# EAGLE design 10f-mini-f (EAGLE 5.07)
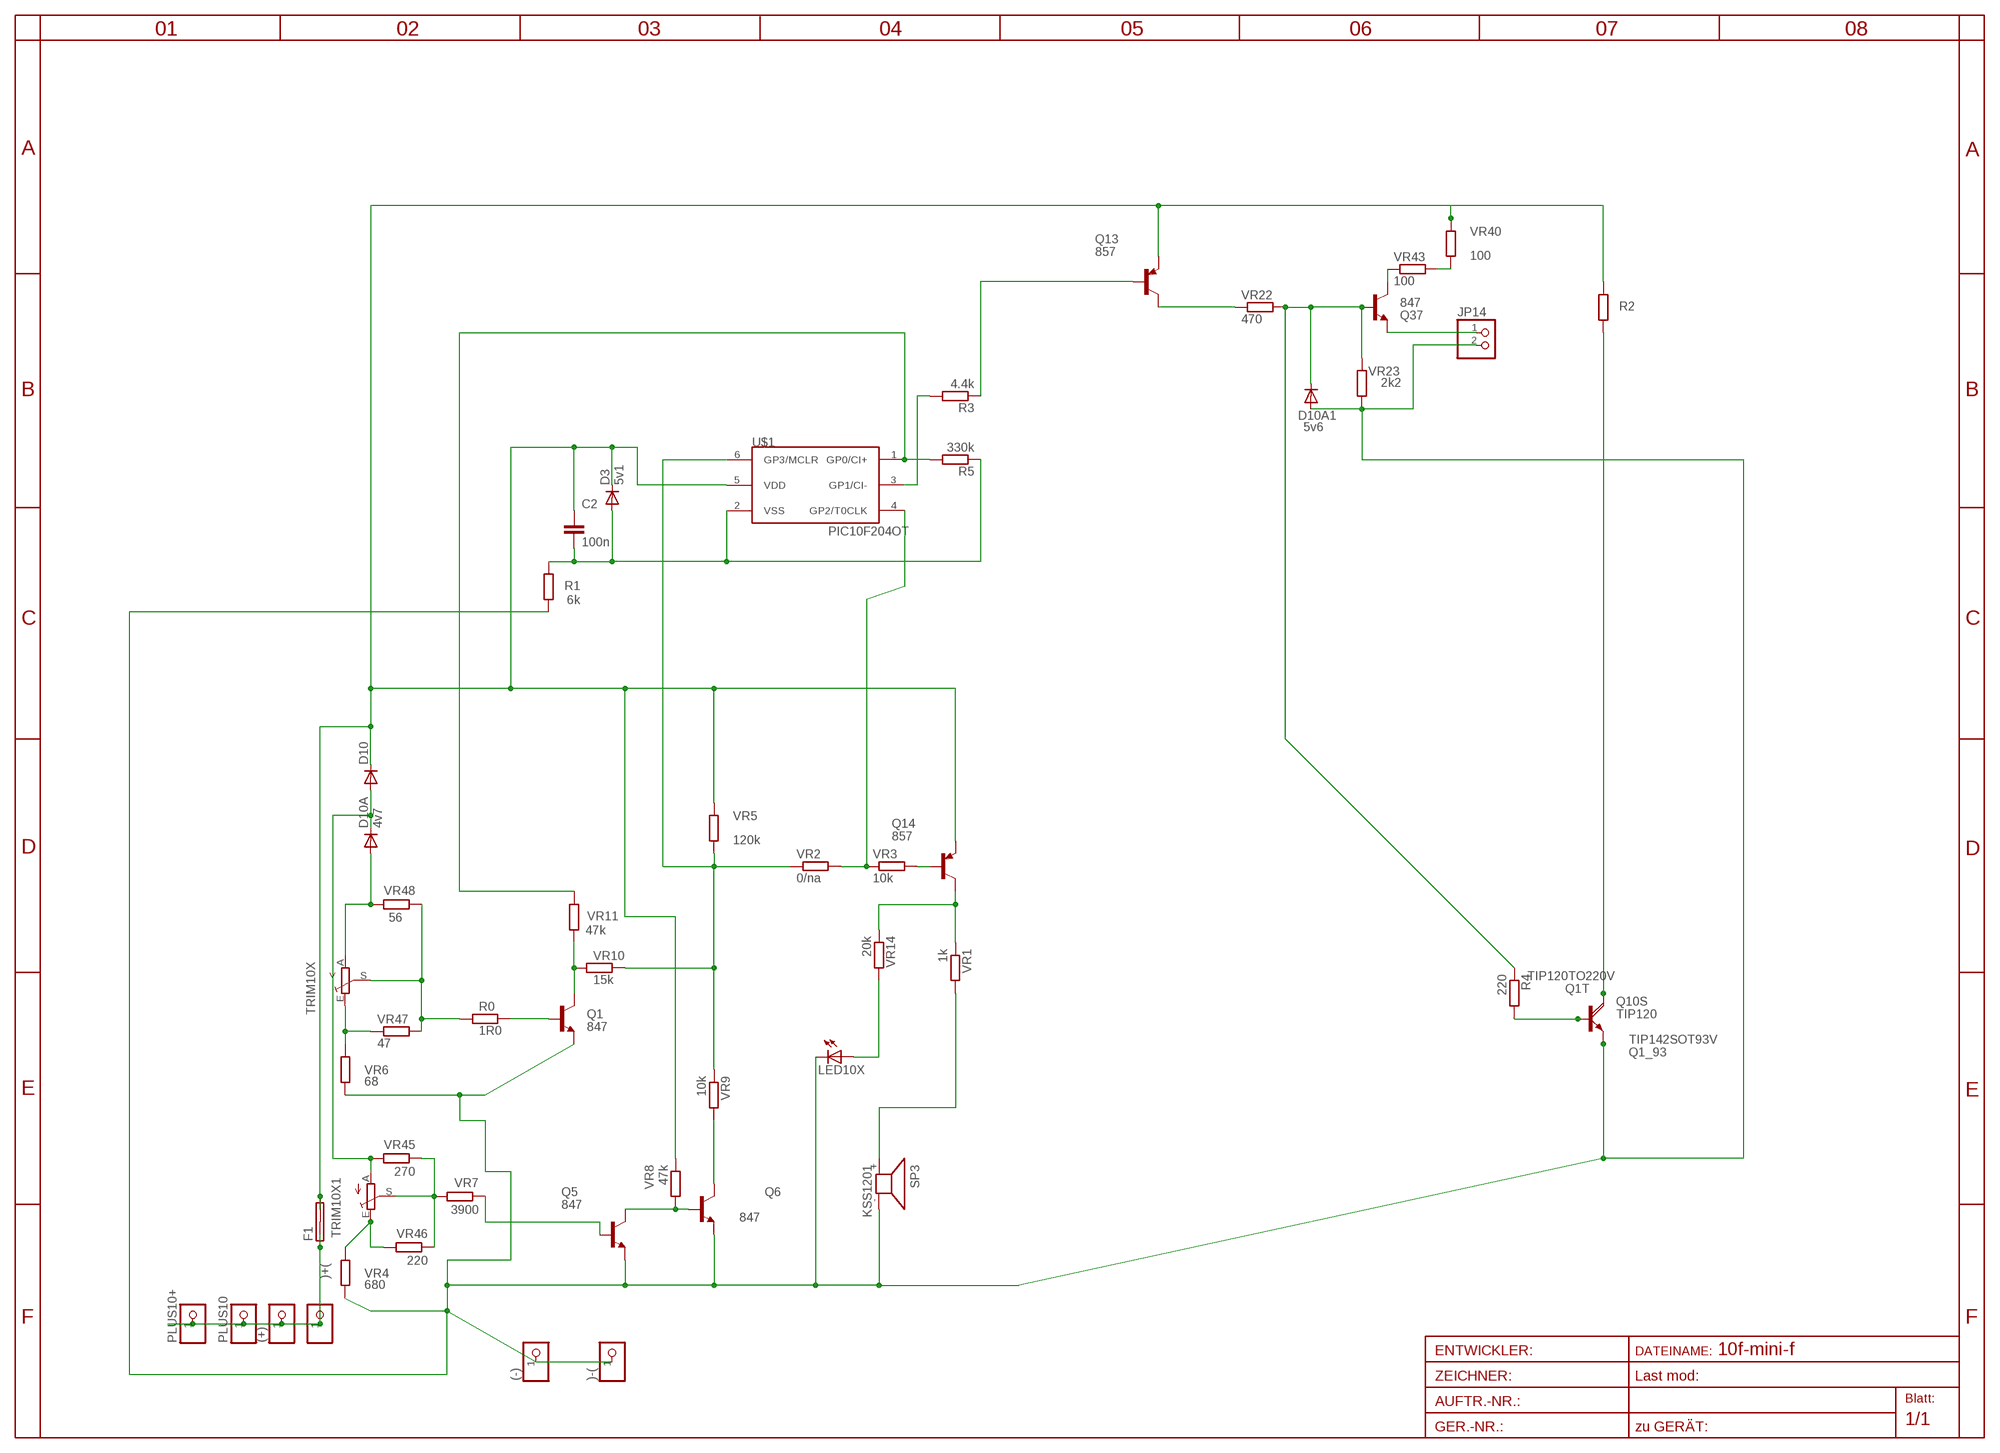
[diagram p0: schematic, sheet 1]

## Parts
(+)  PINHD-1X14.5MM  [1X4MM5]
(-)  PINHD-1X14.5MM  [1X4MM5]
)+(  PINHD-1X11X0.4  [1X01]
)-(  PINHD-1X11X0.4  [1X01]
C2  100n  C-EUC0805  [C0805]
D3  5v1  DIODE-MINIMELF  [MINIMELF]
D10  DIODE-MINIMELF  [MINIMELF]
D10A  4v7  DIODE-MINIMELF  [MINIMELF]
D10A1  5v6  DIODE-MINIMELF  [MINIMELF]
F1  SHK20L7MM5  [7MM5]
JP14  PINHD-1X2STR  [1X02]
LED10X  LEDCHIPLED_1206  [CHIPLED_1206]
PLUS10  PINHD-1X14.5MM  [1X4MM5]
PLUS10+  PINHD-1X11X0.4  [1X01]
Q1  847  BC847CSMD  [SOT23]
Q1_93  TIP142SOT93V  [SOT93V]
Q1T  TIP120TO220V  [TO220AV]
Q5  847  BC847CSMD  [SOT23]
Q6  847  BC847CSMD  [SOT23]
Q10S  TIP120  TIP120DPAK  [D-PAK_TO252AA]
Q13  857  BC857CSMD  [SOT23-BEC]
Q14  857  BC857CSMD  [SOT23-BEC]
Q37  847  BC847CSMD  [SOT23]
R0  1R0  R-EU_R1206  [R1206]
R1  6k  R-EU_R0805  [R0805]
R2  R-EU_CERAM40  [CERAM40]
R3  4.4k  R-EU_R0805  [R0805]
R4  220  R-EU_R0805  [R0805]
R5  330k  R-EU_R0805  [R0805]
SP3  KSS1201  KSS12017MM  [KSS1202]
TRIM10X  TRIM_EU-S64W  [S64W]
TRIM10X1  TRIM_EU-S64W  [S64W]
U$1  PIC10F204OT  [SOT23-6]
VR1  1k  R-EU_R0805  [R0805]
VR2  0/na  R-EU_R0805  [R0805]
VR3  10k  R-EU_R1206  [R1206]
VR4  680  R-EU_R1206  [R1206]
VR5  120k  R-EU_R0805  [R0805]
VR6  68  R-EU_R1206  [R1206]
VR7  3900  R-EU_M1206  [M1206]
VR8  47k  R-EU_R1206  [R1206]
VR9  10k  R-EU_R0805  [R0805]
VR10  15k  R-EU_R1206  [R1206]
VR11  47k  R-EU_R0805  [R0805]
VR14  20k  R-EU_R0805  [R0805]
VR22  470  R-EU_R0805  [R0805]
VR23  2k2  R-EU_R0805  [R0805]
VR40  100  R-EU_R1206  [R1206]
VR43  100  R-EU_R1206  [R1206]
VR45  270  R-EU_R0805  [R0805]
VR46  220  R-EU_R1206  [R1206]
VR47  47  R-EU_R0805  [R0805]
VR48  56  R-EU_R0805  [R0805]

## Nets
B: R0.1 TRIM10X.S VR47.2 VR48.1
BUZZ+: SP3.+ VR1.2
FPLUS: C2.1 D3.C D10.C F1.2A F1.2B Q13.E Q14.E R2.2 U$1.5(VDD) VR5.1 VR8.1 VR40.1
GP3: U$1.4(GP2/T0CLK) VR2.2 VR3.1
INPLUS: (+).1 )+(.1 F1.1A F1.1B PLUS10+.1 PLUS10.1
N$1: R3.2 U$1.3(GP1/CI-)
N$2: Q1.3(C) VR10.1 VR11.1
N$3: Q5.3(C) Q6.1(B) VR8.2
N$4: LED10X.A VR14.2
N$5: Q6.3(C) VR9.2
N$6: U$1.6(GP3/MCLR) VR2.1 VR5.2 VR9.1 VR10.2
N$7: Q1.1(B) R0.2
N$8: Q14.C VR1.1 VR14.1
N$10: Q14.B VR3.2
N$14: D10A.A TRIM10X.A VR48.2
N$17: D10.A D10A.C TRIM10X1.A VR45.2
N$22: TRIM10X1.S VR7.2 VR45.1 VR46.1
N$23: Q13.B R3.1
N$24: TRIM10X1.E VR4.1 VR46.2
N$25: Q1_93.B Q1T.B Q10S.1(B) R4.2
N$128: TRIM10X.E VR6.1 VR47.1
N$136: JP14.1 Q37.2(E)
N$138: R5.2 U$1.1(GP0/CI+) VR11.2
N$159: Q13.C VR22.1
N$163: VR40.2 VR43.2
N$164: Q37.3(C) VR43.1
N$168: Q5.1(B) VR7.1
N$179: D10A1.C Q37.1(B) R4.1 VR22.2 VR23.1
Q10C: Q1_93.C Q1T.C Q10S.4(C) R2.1
VSS: (-).1 )-(.1 D10A1.A JP14.2 LED10X.C Q1.2(E) Q1_93.E Q1T.E Q5.2(E) Q6.2(E) Q10S.3(E) R1.1 SP3.- VR4.2 VR6.2 VR23.2
VSS1: C2.2 D3.A R1.2 R5.1 U$1.2(VSS)

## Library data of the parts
(+) (-) )+( )-( PLUS10 PLUS10+ = pinhead:PINHD-1X1: PIN HEADER
C2 = rcl:C-EU: CAPACITOR, European symbol
D3 D10 D10A D10A1 = diode:DIODE-: DIODE
F1 = fuse:SHK20L: FUSE HOLDER 5 x 20 mm, SH contact, SHH1 Schukat, E1073 Buerklin
JP14 = pinhead:PINHD-1X2: PIN HEADER
LED10X = led:LED: LED
Q1 Q5 Q6 Q37 = transistor-npn:BC847*: NPN Transistor
Q1_93 = transistor-power:TIP142: NPN DARLINGTON TRANSISTOR
Q1T Q10S = transistor-power:TIP120: NPN DARLINGTON TRANSISTOR
Q13 Q14 = transistor-pnp:BC857*: PNP Transistror
R0 R1 R3-R5 VR1-VR11 VR14 VR22 VR23 VR40 VR43 VR45-VR48 = rcl-2:R-EU_: RESISTOR, European symbol
R2 = rcl:R-EU_: RESISTOR, European symbol
SP3 = buzzer:KSS1201: SPEAKER
TRIM10X TRIM10X1 = pot:TRIM_EU-: POTENTIOMETER
U$1 = microchip-3:PIC10F2*: uPC nW 0,25/0,5k Program Flash memory Comparator

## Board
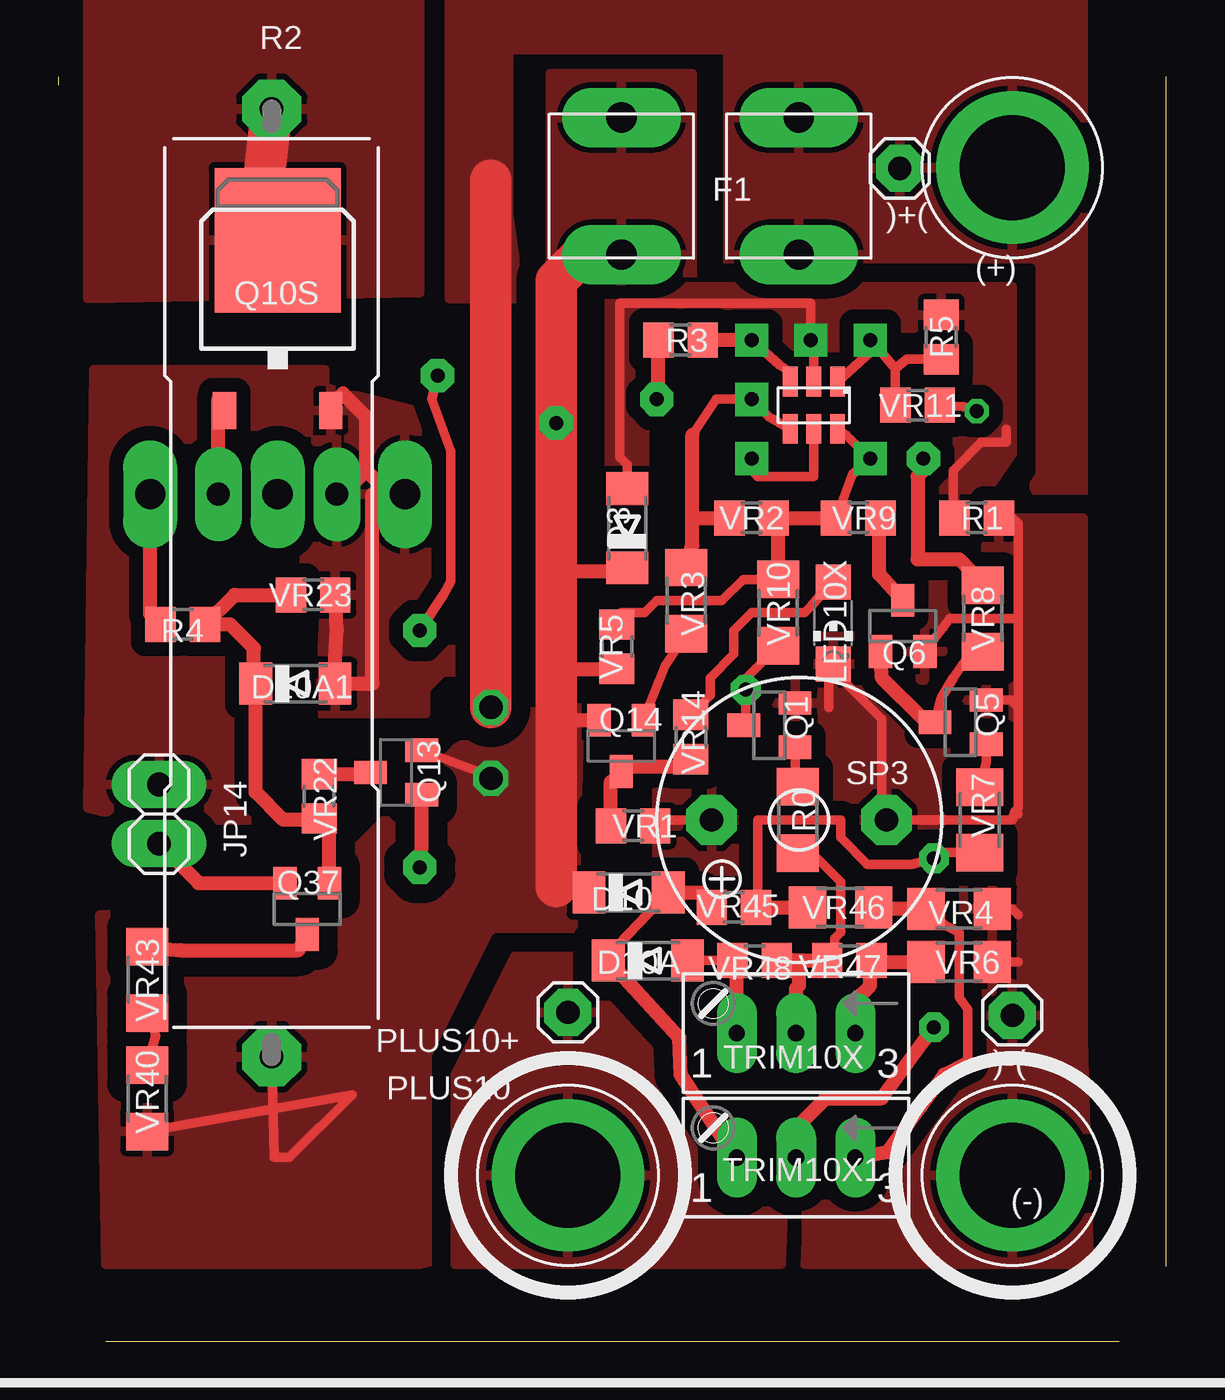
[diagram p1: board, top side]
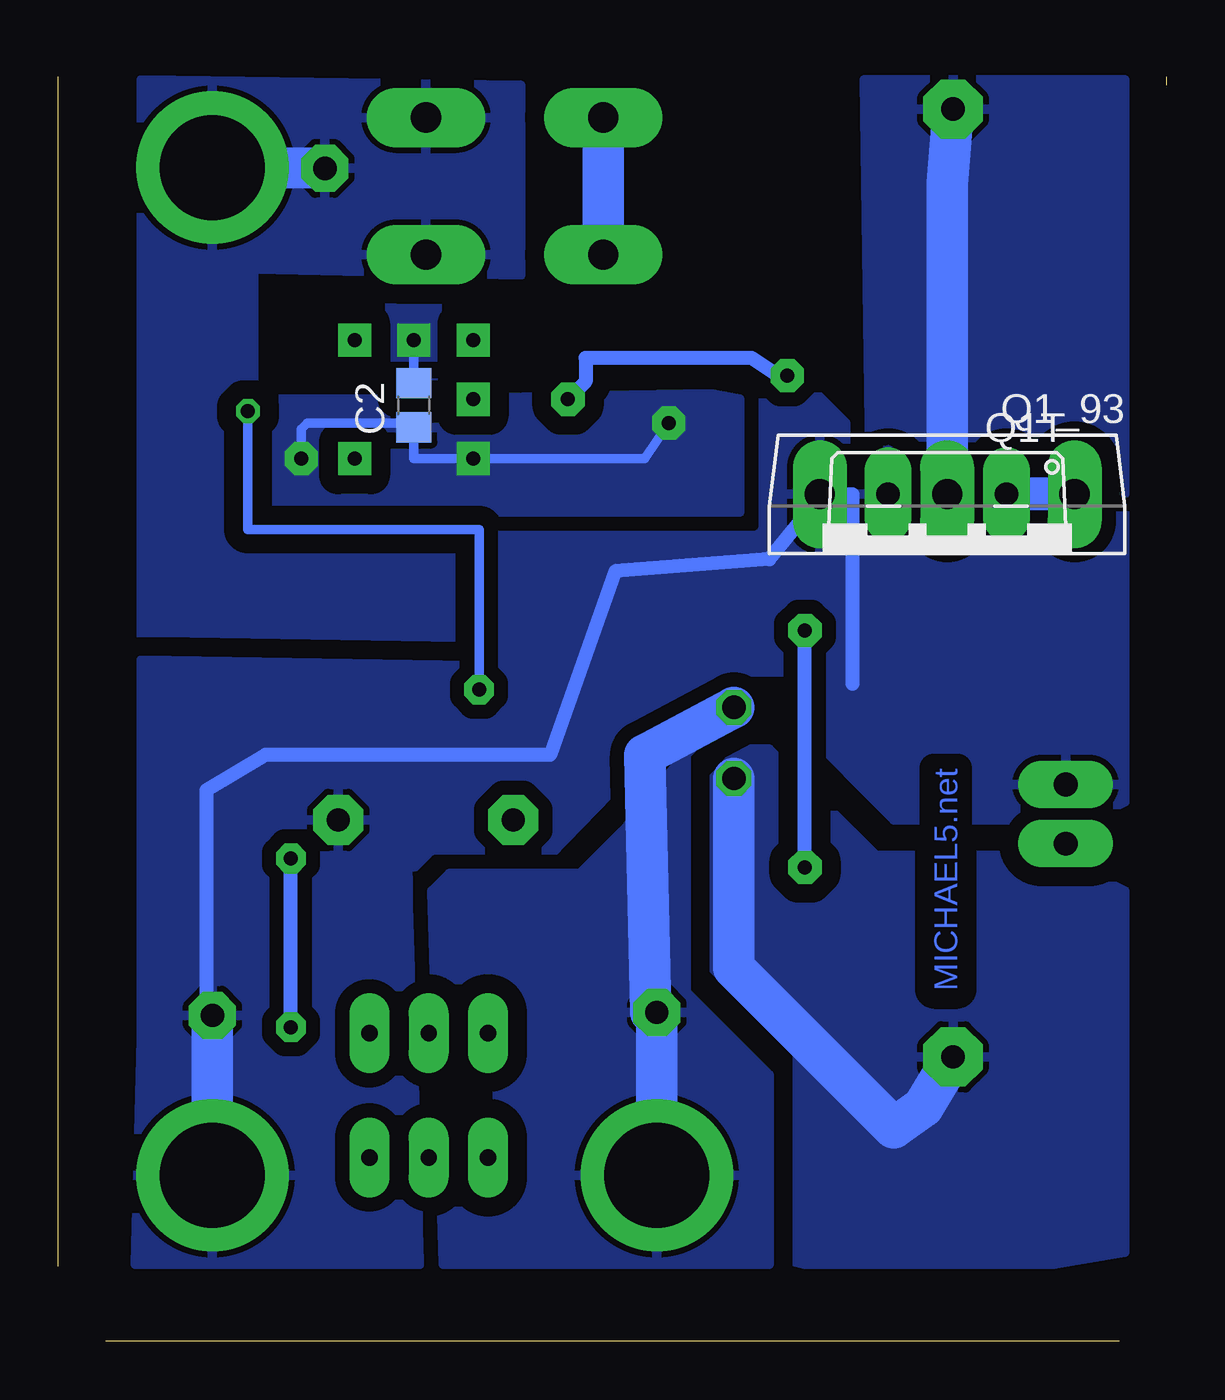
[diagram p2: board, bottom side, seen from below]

Size 47.5 x 54.22 mm. Coordinates in mm from the lower left corner, seen from the top.
Outline: 2.03,0 45.47,0
Outline: 47.5,3.22 47.5,54.22
Outline: 0,54.22 0,53.85
Copper layers (1*16): Top 0.035mm / dielectric 1.5mm / Bottom 0.035mm
Design rules "default *": minimum track width 8mil, minimum drill 4mil, track to track 8mil, track to pad 8mil, pad to pad 8mil, via to via 8mil, smd to smd 8mil, copper to edge 40mil, drill to drill 8mil, minimum pad ring 20mil, minimum via ring 8mil, stop-mask expansion 4mil, vias tented up to drill 0mil, thermal gap 10mil

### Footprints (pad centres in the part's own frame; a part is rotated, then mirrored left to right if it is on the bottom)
1X4MM5 = drill 4.5 pad 6.35 round: 1 0,0
1X01 = drill 1 pad 1.676 octagon: 1 0,0
C0805 = smd 1.3 x 1.5: 1 -0.95,0; 2 0.95,0
MINIMELF = smd 1.4 x 1.8: A 1.7,0; C -1.7,0
7MM5 = drill 1.3 pad 2.54 long: 1A -3.8,2.94; 1B -3.8,-2.94; 2A 3.8,2.94; 2B 3.8,-2.94
1X02 = drill 1.016 pad 1.676 long: 1 -1.27,0; 2 1.27,0
CHIPLED_1206 = smd 1.5 x 1.5: A 0,-1.75; C 0,1.75
SOT23 = smd 1 x 1.4: 1 -0.95,-1.1; 2 0.95,-1.1; 3 0,1.1
SOT93V = drill 1.3 pad 1.676 long: B -5.461,-2.54; C 0,-2.54; E 5.461,-2.54
TO220AV = drill 1 pad 1.27 long: B -2.54,-2.54; C 0,-2.54; E 2.54,-2.54
D-PAK_TO252AA = smd 1 x 1.6: 1 -2.28,-4.8; 3 2.28,-4.8 | smd 5.4 x 6.2: 4 0,2.5
SOT23-BEC = smd 1 x 1.4: B -0.95,-1.1; C 0,1.1; E 0.95,-1.1
R1206 = smd 1.6 x 1.803: 1 -1.422,0; 2 1.422,0
R0805 = smd 1.3 x 1.5: 1 -0.95,0; 2 0.95,0
CERAM40 = drill 1 pad 2.54 octagon: 1 -20.32,0; 2 20.32,0
KSS1202 = drill 1 pad 2.159 octagon: + 3.75,0; - -3.75,0
S64W = drill 0.7 long: A 2.54,1.27; E -2.54,1.27; S 0,1.27
SOT23-6 = smd 0.635 x 1.27: 1 -1.016,-1.016; 2 0,-1.016; 3 1.016,-1.016; 4 1.016,1.016; 5 0,1.016; 6 -1.016,1.016
M1206 = smd 1.6 x 2: 1 -1.4,0; 2 1.4,0

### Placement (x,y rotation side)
(+)  40.89,50.32 0 top
(-)  40.89,7.11 0 top
)+(  36.07,50.29 0 top
)-(  40.89,13.97 0 top
C2  32.26,40.13 90 bottom
D3  24.38,34.86 90 top
D10  24.45,19.24 0 top
D10A  25.27,16.32 0 top
D10A1  10.16,28.19 0 top
F1  27.94,49.53 180 top
JP14  4.32,22.61 90 top
LED10X  33.21,30.8 180 top
PLUS10  21.84,7.11 0 top
PLUS10+  21.84,14.1 0 top
Q1  30.48,26.42 90 top
Q1_93  9.4,33.78 180 bottom
Q1T  9.4,33.78 180 bottom
Q5  38.67,26.54 90 top
Q6  36.2,30.67 0 top
Q10S  9.4,44.7 0 top
Q13  14.48,24.38 90 top
Q14  24.13,25.53 180 top
Q37  10.67,18.54 180 top
R0  31.69,22.35 90 top
R1  39.37,35.31 180 top
R2  9.14,32.51 270 top
R3  26.67,42.93 0 top
R4  5.33,30.73 180 top
R5  37.85,43.05 270 top
SP3  31.75,22.35 180 top
TRIM10X  31.62,14.48 180 top
TRIM10X1  31.62,9.14 180 top
U$1  32.38,40.13 180 top
VR1  24.64,22.1 0 top
VR2  29.72,35.31 180 top
VR3  26.92,31.75 270 top
VR4  38.61,18.54 0 top
VR5  23.94,29.78 90 top
VR6  38.61,16.26 0 top
VR7  39.5,22.35 270 top
VR8  39.62,30.99 270 top
VR9  34.29,35.31 0 top
VR10  30.86,31.24 90 top
VR11  36.83,40.13 180 top
VR14  27.11,25.91 90 top
VR22  11.18,23.37 270 top
VR23  10.92,32 0 top
VR40  3.81,10.41 90 top
VR43  3.81,15.49 270 top
VR45  28.96,18.61 180 top
VR46  33.53,18.61 0 top
VR47  33.91,16.32 180 top
VR48  29.84,16.32 180 top

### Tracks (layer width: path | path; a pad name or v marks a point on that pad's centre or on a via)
B
  Top 0.406: VR47.2 33.27,16.64 33.27,17.27 33.53,17.53 33.53,19.69 32.16,21.06 R0.1 | 31.62,15.11 31.75,15.24
  Top 0.61: 32,16.32 VR48.1 | 32,16.32 VR47.2 | TRIM10X.S 31.62,15.11 | 31.75,15.24 31.75,16.07 32,16.32
BUZZ+
  Top 0.406: SP3.+ 25.84,22.35 VR1.2
  pour Top (isolate 0.61): 26.42,24.13 29.97,24.13 30.48,23.62 30.48,20.07 30.23,19.81 26.42,19.81 25.65,20.57 25.65,23.62
FPLUS  (via drill 0.6 pad 1.42, 1 pad 1.42)
  Top 0.406: 39.12,33.02 VR8.1 | U$1.5 32.38,37.08 29.97,37.08 29.72,37.34 v29.72,37.85 | Q13.E 18.29,24.32 18.22,24.32 v18.54,24.13 | VR40.1 12.6,10.57 9.91,7.87 9.25,7.87 R2.2 | 21.34,32.77 21.87,32 | VR5.1 23.81,28.96 | 24.24,33.02 D3.C
  Top 0.61: 39.12,33.02 38.61,33.53 36.83,33.53 36.83,37.08 37.08,37.34 v37.08,37.85 | 21.34,33.02 24.24,33.02 | VR5.1 21.34,28.83 21.34,28.7 | Q14.E 21.34,26.63 21.34,26.67
  Top 1.778: 21.34,19.49 21.34,26.67 21.34,28.7 21.34,32.77 21.34,33.02 v21.34,39.37 21.34,45.47 22.35,46.48 24.03,46.48 F1.2A
  Bottom 0.406: v37.08,37.85 37.08,39.12 36.83,39.37 32.26,39.37 C2.1 32.26,37.85 v29.72,37.85 22.35,37.85 v21.34,39.37
  Bottom 0.61: C2.1 32.38,39.18
  Bottom 1.778: R2.2 10.41,10.05 11.68,9.14 18.54,16 v18.54,24.13 | F1.2A F1.2B
  pour Bottom (isolate 0.813, rank 2): 15.49,3.3 4.83,3.3 1.78,3.81 1.78,19.3 4.32,20.57 4.57,20.83 12.45,20.83 17.02,25.4 19.3,25.4 20.32,24.38 20.32,14.99 16.51,11.18 16.51,3.56
  pour Top (isolate 0.813, rank 2): 15.49,3.3 2.03,3.3 1.78,18.29 12.45,18.29 12.45,20.83 17.02,25.4 19.56,26.92 22.35,27.18 22.1,16.26 16.51,11.18 16.51,3.56
  pour Bottom (isolate 0.813): 18.29,35.56 18.29,40.39 19.56,40.64 32.26,40.39 38.61,40.39 38.61,35.56
  pour Top (rank 4): 21.08,54.36 27.18,54.36 27.18,45.47 21.08,45.47
GP3  (via drill 0.6 pad 1.42)
  Top 0.406: U$1.4 30.48,39.62 v29.72,40.39 28.19,40.39 27.18,38.86
  Top 0.61: 27.18,35.31 27.18,38.86 | 27.18,35.31 VR2.2 | 27.18,35.31 27.18,34.12 VR3.1
INPLUS  (via drill 1 pad 1.42)
  Top 1.778: v18.54,27.18 18.54,49.78
  Bottom 1.778: PLUS10.1 PLUS10+.1 22.1,14.1 22.35,25.15 v18.54,27.18 | )+(.1 (+).1
  pour Bottom (isolate 0.813): 18.8,27.43 23.11,22.1 25.15,20.07 30.73,20.07 31.5,19.3 30.99,3.3 17.02,3.3 17.02,11.43 20.57,14.99 20.57,25.15 20.07,25.65
  pour Bottom (isolate 0.813, rank 3): 43.94,54.1 43.94,29.72 29.97,29.72 29.46,30.23 29.46,35.31 29.97,35.81 38.61,35.56 39.12,36.32 39.12,45.97 27.69,45.72 27.69,53.85
  pour Top (isolate 0.813): 31.5,16.51 30.99,3.3 17.02,3.3 17.02,11.43 19.56,16.51
  pour Top (isolate 0.813, rank 3): 16.76,58.42 34.8,58.42 43.94,58.42 43.94,35.56 29.46,35.31 29.97,35.81 38.61,35.56 39.12,36.32 38.61,46.23 28.7,46.23 28.7,55.37 19.3,55.37 19.3,48.26 19.81,44.7 16.76,44.7
N$1
  Top 0.406: 29.72,42.93 30.92,41.85 31.31,41.59 U$1.3
  Top 0.61: 29.72,42.93 R3.2
N$2  (via drill 0.6 pad 1.02, 0.6 pad 1.27)
  Top 0.406: VR11.1 38.8,40.07 v39.37,39.88 | 30.86,29.34 VR10.1 29.46,28.42 v29.46,27.94 29.46,26.5 Q1.3
  Bottom 0.406: v29.46,27.94 29.46,34.8 39.37,34.8 v39.37,39.88
N$3
  Top 0.406: VR8.2 39.47,30.07 38.35,28.45 37.85,27.58 Q5.3
  Top 0.61: Q6.1 35.31,28.45 37.08,26.67 37.45,26.67 Q5.3
N$4
  Top 0.406: VR14.2 27.37,27.11 27.94,27.69 27.94,28.45 28.96,29.46 28.96,30.48 29.72,31.24 32,31.24 32.26,31.5 32.77,32.1 LED10X.A
N$5
  Top 0.406: 35.56,35.12 VR9.2
  Top 0.61: Q6.3 35.18,32.89 35.18,35.05 35.56,35.12
N$6
  Top 0.406: VR9.1 34.04,37.15 34.8,37.85 33.78,38.86 U$1.6 | VR10.2 29.36,32.66 28.45,31.75 25.65,31.75 25.15,31.24 24.13,31.25 VR5.2 | 30.86,35.11 VR2.1
  Top 0.61: VR2.1 VR9.1 | VR10.2 30.86,35.11
N$7
  Top 0.406: Q1.1 31.58,23.88 R0.2
N$8
  Top 0.406: 26.92,24.64 27.31,25.02 VR14.1 | 24.53,24.64 Q14.C 23.69,23.99
  Top 0.61: 24.53,24.64 26.92,24.64 | VR1.1 23.69,23.99
N$9  (via drill 0.6 pad 1.42)
  other vias: 34.8,37.85
N$10
  Top 0.406: Q14.B 26.02,28.98 VR3.2
N$11  (via drill 0.6 pad 1.42)
  other vias: 34.8,42.93
N$14
  Top 0.406: 29.08,16.26 VR48.2 D10A.A
  Top 0.61: TRIM10X.A 29.08,16.26
N$17
  Top 0.406: 27.56,19.24 VR45.2 | D10A.C 23.57,16.54 D10.A
  Top 0.61: D10.A 27.56,19.24 | D10A.C 26.62,13 26.67,11.43 28.45,8.76 TRIM10X1.A
N$22  (via drill 0.6 pad 1.27)
  Top 0.406: VR45.1 29.97,18.61 29.97,22.35 33.53,22.35 33.53,21.59 34.67,20.45 36.58,20.45 v37.53,20.7 37.91,20.95 VR7.2
  Top 0.61: 29.97,18.61 VR46.1 | TRIM10X1.S 31.62,9.14 32.89,10.41 35.31,10.41 v37.53,13.46
  Bottom 0.61: v37.53,13.46 v37.53,20.7
N$23  (via drill 0.6 pad 1.42)
  Top 0.406: v15.49,30.48 16.51,32 16.83,32.58 16.83,38.16 16,40.39 v16.26,41.4
  Top 0.61: R3.1 25.72,40.71 v25.65,40.39 | Q13.B 15.58,21.17 v15.49,20.32
  Bottom 0.61: v16.26,41.4 16.26,41.15 17.78,42.16 24.89,42.16 24.89,41.15 v25.65,40.39 | v15.49,20.32 v15.49,30.48
N$24
  Top 0.406: 38.99,11.94 38.99,14.22 38.61,14.73 38.61,17.53 38.1,17.78 37.44,18.29 VR4.1 | 35.01,18.54 VR46.2
  Top 0.61: TRIM10X1.E 35.56,8.13 37.97,11.43 38.99,11.94 | VR4.1 35.01,18.54
N$25
  Top 0.61: Q1_93.B 3.94,31.18 R4.2 | Q1T.B 6.86,40.41 Q10S.1
  Bottom 1.422: Q1_93.B Q1T.B
N$128
  Top 0.406: 34.8,16.25 VR47.1 34.8,16.26
  Top 0.61: TRIM10X.E 34.16,14.6 34.8,15.24 34.8,16.25 | 34.8,16.26 VR6.1
N$136
  Top 0.61: Q37.2 6.01,19.64 JP14.1
N$138
  Top 0.406: 35.87,41.71 VR11.2 | 35.87,41.71 35.12,42.61 34.8,42.93 34.8,42.42 U$1.1 | R5.2 36.37,42.1 35.87,41.71
N$159
  Top 0.61: VR22.1 12.68,24.32 Q13.C
N$163
  Top 0.406: VR40.2 4.17,13.11 VR43.2
N$164
  Top 0.61: VR43.1 5.23,16.76 10.29,16.76 Q37.3
N$168
  Top 0.406: Q5.1 39.77,24.79 VR7.1
N$179
  Top 0.61: Q37.1 11.62,21.98 VR22.2 11.11,22.35 9.65,22.35 8.46,23.54 D10A1.C 8.38,28.27 8.38,29.72 7.37,30.73 R4.1 7.55,32 VR23.1
Q10C
  Top 1.422: 9.65,47.24 9.65,47.71 Q10S.4
  Top 1.778: R2.1 8.64,48.26 9.65,47.24
  Bottom 1.778: Q1_93.C 9.4,49.64 R2.1
  pour Top (isolate 0.813): 1.27,58.17 15.49,58.42 15.49,44.96 1.27,44.7
  pour Bottom (isolate 0.813): 1.78,54.1 12.95,54.1 12.7,36.32 1.78,36.32
VDF  (via drill 0.6 pad 1.42)
  other vias: 29.72,42.93
VSS
  Top 0.406: VR4.2 40.89,18.54 41.15,18.29 | VR6.2 41.15,16.26 | 41.02,22.73 41.15,22.61 | 41.02,22.73 40.89,22.35 SP3.- 35.31,22.55 35.31,26.67 33.21,28.77 LED10X.C 33.02,28.86 33.02,27.18 | Q5.2 40.83,27.49 41.15,27.18 | 41.15,27.18 41.15,22.86 41.02,22.73 | R1.1 40.89,35.31 41.15,35.05 41.15,30.99 | 41.15,27.18 41.15,30.99 | Q6.2 38.21,30.99 41.15,30.99
  Top 0.61: VR23.2 11.94,30.48 11.86,29.29 D10A1.A 13.46,28.19 13.46,36.32 14.99,36.2 Q1_93.E 14.22,36.32 13.21,37.34 | Q1T.E 12.19,36.32 13.21,37.34 | 13.21,37.34 13.21,39.62 12.19,40.64 11.96,40.39 Q10S.3
  Bottom 0.61: )-(.1 41.15,14.22 41.15,23.62 38.61,25.15 26.42,25.15 23.62,33.02 17.02,33.53 14.86,36.2 Q1_93.E 13.46,36.32 13.46,28.19
  Bottom 1.778: )-(.1 (-).1
  pour Top (isolate 0.61): 32.51,29.72 32.51,27.69 31.5,26.67 31.5,24.89 35.56,20.83 41.15,20.83 41.4,21.08 41.4,23.62 40.64,24.38 38.1,24.38 38.1,27.18 36.58,27.94
  pour Bottom (isolate 0.61, rank 2): 44.2,3.3 43.94,12.95 43.94,29.21 28.45,28.96 28.45,36.58 18.8,36.83 16.51,42.16 13.21,38.86 1.78,36.07 1.78,23.11 3.3,22.35 11.68,22.35 15.75,26.42 15.75,27.94 16.51,28.7 18.8,28.7 26.42,20.83 32.51,20.32 32,3.3
  pour Top (isolate 0.61, rank 2): 44.2,3.3 43.94,12.95 43.94,35.31 37.08,35.31 37.08,30.23 29.46,30.23 29.46,36.58 27.43,36.83 11.43,40.89 11.43,41.66 1.52,41.66 1.27,22.86 3.3,22.35 9.4,22.35 9.65,31.75 11.43,32 11.18,26.92 15.75,26.92 15.75,27.94 16.51,28.7 18.8,28.7 26.42,20.83 32.51,20.32 32,3.3
VSS1  (via drill 0.6 pad 1.42)
  Top 0.406: 40.64,39.12 40.64,38.54 39.56,38.54 38.35,37.34 38.35,35.49 | U$1.2 32.38,42.67 v32.26,42.93 32.26,44.51 24.07,44.51 24.07,37.91 24.38,37.59 D3.A | R5.1 38.1,44.13
  Top 0.61: R1.2 38.35,35.49
  Bottom 0.406: v32.26,42.93 C2.2
  pour Top (isolate 0.61): 23.62,37.34 23.62,44.96 24.13,45.21 40.89,45.21 40.89,38.04 39.37,35.81 37.59,35.81 37.59,41.66 38.35,42.42 38.35,42.93 37.85,43.43 34.29,43.43 33.27,42.42 31.24,42.42 31.24,42.67 30.48,43.43 25.65,43.43 25.15,42.93 25.15,37.08
  pour Bottom (isolate 0.813, rank 2): 27.69,44.7 38.35,44.7 38.35,41.4 38.1,41.4 27.69,41.4

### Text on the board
Bottom: MICHAEL5.net
tTest: 4v4
Document: 1m | 10u | 10u | 300u | 2mA | 500u | 1m | 2m | 300u | 300u | 30u | 5m | 14m | 12m | 500u | 5m | 5m | 5m | 5m | 5m | 5m | 40m | 40m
